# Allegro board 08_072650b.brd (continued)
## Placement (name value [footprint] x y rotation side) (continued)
DS20  APHHS1005LSECK/J3-PF  [LED0402H24]  5.15 77.42 0 top
DS21  APHHS1005LSECK/J3-PF  [LED0402H24]  5.15 78.94 0 top
DS22  APHHS1005LCGCK  [LED0402_A]  5.15 75.77 0 top
DS23  APHHS1005LCGCK  [LED0402_A]  5.15 80.47 0 top
DS24  APHHS1005LCGCK  [LED0402_A]  5.15 82.12 0 top
DS25  APHHS1005LCGCK  [LED0402_A]  5.15 83.77 0 top
DS26  APHHS1005LCGCK  [LED0402_A]  5.15 85.29 0 top
DS27  APHHS1005LCGCK  [LED0402_A]  5.15 86.82 0 top
DS29  SML-LX1206IW-TR  [LEDSML126W63H43]  43.18 190.58 90 top
DS31  APHHS1005LSECK/J3-PF  [LED0402H24]  206.88 113.08 90 top
E1  120OHM  [L0402]  10.39 229.39 270 bottom
E2  600OHM  [L0603_A]  131.83 153.52 180 bottom
E2B  120OHM  [L0402#2]  34.61 232.11 180 bottom
E3  600OHM  [L0603_A]  128.4 166.5 270 bottom
E4  600OHM  [L0603_A]  127.71 174.47 270 bottom
E5  600OHM  [L0603_A]  119.79 174.42 270 bottom
E7  120OHM  [L0402#2]  6.71 224.59 0 bottom
E8  120OHM  [L0402]  14.58 231.29 90 top
E9  120OHM  [L0402]  23.24 223.88 0 bottom
E10  120OHM  [L0402#2]  16.61 231.83 90 top
E11  120OHM  [L0402]  18.14 219.35 90 top
E12  120OHM  [L0402]  11.4 216.31 270 bottom
E13  120OHM  [L0402]  23.6 218.85 270 bottom
E14  120OHM  [L0402]  20.29 225.32 270 top
E15  30OHM  [L0402]  30.18 195.33 270 top
E20  50OHM AT 100MEGHZ  [L1206-3]  171.86 204.06 180 bottom
E21  470OHM AT 100MEGHZ  [L1206H71]  229.41 173.53 270 top
E22  470OHM AT 100MEGHZ  [L1206H71]  225.6 173.53 270 top
E23  50OHM AT 100MEGHZ  [L1206-3]  171.42 216.56 180 bottom
E24  50OHM AT 100MEGHZ  [L1206-3]  175.69 225.96 180 bottom
E26  50OHM AT 100MEGHZ  [L1206-3]  175.64 222.02 180 bottom
E27  50OHM AT 100MEGHZ  [L1206-3]  175.69 229.59 180 bottom
E30  50OHM AT 100MEGHZ  [L1206-3]  184.91 75.12 180 top
E31  50OHM AT 100MEGHZ  [L1206-3]  190.92 71.81 270 top
EXT_HMCREF  142-0701-201  [CNJOHNSON142-0701-201]  47.23 276.81 180 top
EXT_SYNC  142-0701-201  [CNJOHNSON142-0701-201]  8.56 243.32 0 top
EXT_SYS_N  142-0701-201  [CNJOHNSON142-0701-201]  15.21 276.66 0 top
EXT_SYS_P  142-0701-201  [CNJOHNSON142-0701-201]  31.12 276.68 0 top
EXT_TRIG  142-0701-201  [CNJOHNSON142-0701-201]  8.71 259.92 0 top
F1  12A  [F1206H46]  211.48 262.61 270 top
FANPWM  WHT  [CNKEY5001TP]  216.53 222.88 0 top
FMC12I  WHT  [CNKEY5001TP]  224.03 252.48 0 top
FMC12O  WHT  [CNKEY5001TP]  89.56 22.43 0 top
GND1  BLK  [CNKEY5001TP]  9.27 100.97 0 top
GND2  BLK  [CNKEY5001TP]  200.46 236.4 0 top
GND3  BLK  [CNKEY5001TP]  57.81 260.99 180 bottom
GND4  BLK  [CNKEY5001TP]  49.99 194.84 0 top
GND5  BLK  [CNKEY5001TP]  4.34 49 180 bottom
GND6  BLK  [CNKEY5001TP]  218.06 38.07 180 bottom
GND7  BLK  [CNKEY5001TP]  173.02 82.4 0 top
GND8  BLK  [CNKEY5001TP]  174.98 164.64 180 bottom
J3  85305-0232  [CNSMASQ197H161]  144.2 10.24 270 top
J12  142-0701-201  [CNJOHNSON142-0701-201]  41.58 259.82 0 top
J13  142-0701-201  [CNJOHNSON142-0701-201]  26.35 259.83 0 top
J17  142-0701-201  [CNJOHNSON142-0701-201]  49.61 247.28 270 top
J18  142-0701-201  [CNJOHNSON142-0701-201]  65.09 247.38 90 top
JP1  0  [R0402]  11.63 93.91 270 top
JP2  0  [R0402]  42.37 103.07 270 top
L1  1.3NH  [L0201_A]  126.24 150.52 180 bottom
L2  4.7uH  [L0806]  191.26 191.72 0 bottom
L3  1.3NH  [L0201_A]  121.97 151.54 0 bottom
L4  1.3NH  [L0201_A]  123.42 151.54 0 bottom
L5  72NH  [LSML299W295H195]  188.59 48.03 180 top
L6  1UH  [L0806_DFE]  84.38 212.87 180 top
L8  0.13UH  [LSMSQ157H122]  190.25 60.92 180 top
L9  0.13UH  [LSMSQ157H122]  200.33 82.17 90 top
L10  1.3NH  [L0201_A]  125.07 150.52 180 bottom
L11  0.47UH  [L0603]  160.48 41.3 90 bottom
L15  3.6nH  [L0201]  36.91 218.92 0 top
L16  3.6nH  [L0201]  36.93 218.26 0 top
L17  10UH  [L1210H47]  219.89 253.45 0 top
L18  0.13UH  [LSMSQ157H122]  197.21 74.45 180 top
L19  1UH  [L0806_DFE]  71.04 212.73 180 top
L20  0.33UH  [L1008H47]  109.52 261.21 270 top
L21  0.22UH  [L2520H47]  205.56 101.22 180 top
NOREF  -  []  0 34.04 0 top
NOREF#2  -  []  241.43 33.91 90 top
NOREF#3  -  []  -258.06 -177.93 0 top
NOREF#4  -  []  -258.06 -177.93 0 top
NOREF#5  -  []  6.16 39.88 0 top
NOREF#6  -  []  156.72 0 90 top
NOREF#7  -  []  37.72 119.46 90 top
NOREF#8  -  []  241.36 33.89 90 top
NOREF#9  -  [unnamed#2]  95.4 152.48 0 top
NOREF#10  -  [unnamed#2]  229.36 38.35 0 top
NOREF#11  -  [unnamed#2]  152.86 27.76 90 top
NOREF#12  -  []  0 34.04 0 top
NOREF#13  -  []  141.99 272.92 0 top
NOREF#14  -  [unnamed#2]  234.8 160.07 225 top
NOREF#15  -  []  371.86 -35.69 0 top
NOREF#16  -  []  241.24 289.35 180 top
NOREF#17  -  []  0.06 34.01 0 top
NOREF#18  -  []  86.3 0.04 0 top
NOREF#19  -  [unnamed#2]  117.96 281.99 225 top
NOREF#20  -  []  156.65 0.04 90 top
NOREF#21  -  []  0 289.43 0 top
NOREF#22  -  [unnamed#2]  11.18 284.1 0 top
NOREF#23  -  []  6.16 39.88 0 top
NOREF#24  -  []  156.72 0 0 top
NOREF#25  -  [unnamed#2]  235.2 40.39 225 top
NOREF#26  -  [unnamed#2]  95.4 98.5 0 top
NOREF#27  -  []  131.01 322.3 0 top
NOREF#28  -  []  -12.11 51.06 0 top
NOREF#29  -  [unnamed#2]  5.33 162.56 225 top
NOREF#30  -  []  86.23 0 0 top
NOREF#31  -  [unnamed#2]  149.38 152.48 0 top
NOREF#32  -  []  -258.06 -177.93 0 top
NOREF#33  -  []  86.23 0 0 top
NOREF#34  -  [unnamed#2]  149.38 98.5 0 top
NOREF#35  -  [unnamed#2]  6.16 39.88 225 top
NOREF#36  -  []  152.53 -60.58 0 top
NOREF#37  -  [unnamed#2]  234.8 281.99 225 top
NOREF#38  -  [unnamed#2]  11.18 38.35 0 top
NOREF#39  VAL  [unnamed#3]  202.18 121.26 270 top
NOREF#40  -  []  49.76 -121.69 0 top
NOREF#41  -  [unnamed#2]  5.33 284.48 225 top
NOREF#42  -  [unnamed#2]  89.86 27.76 90 top
NOREF#43  -  []  0.06 289.35 270 top
NOREF#44  -  []  203.53 217.7 180 bottom
P1  ASP-188588-01  [CNSAMTECASP-188588-01]  121.28 25.78 180 bottom
P2  FTSH-108-01-F-DV-K  [CNHDR2X8H251]  49.33 45.49 270 top
P3  FTSH-110-01-L-DV-K  [CNHDR2X10H251]  48.18 66.19 270 top
P4  10103594-0001LF  [CNFCI10103594-0001LF]  0 59.05 90 bottom
P5  DF3EA-4P-2H(51)  [CNHIROSEDF3EA-2P-2H]  237.39 118.57 270 bottom
P7  TSM-103-01-T-SV  [CNSM1X3H380]  236.47 119.43 90 top
P18  CJT-T-P-HH-RA-TH1  [CNSAMTECCJT-T-P-GF-RA-TH1]  3.25 192.23 90 top
P19  CJT-T-P-HH-RA-TH1  [CNSAMTECCJT-T-P-GF-RA-TH1]  3.1 200.28 90 top
P22  39-30-1060  [CNHDRRA2X3H451]  211.48 272.52 0 top
P23  22-11-2032  [CNMOLEX22-23-2031]  231.57 227.66 270 top
PWRDBG  TMM-102-01-G-S-SM  [CNSAMTECTMM-102-01-G-S-SM]  191.16 247.5 180 top
Q1  DMN2300UFL4-7  [DFN6_1_3X1]  235.4 233.55 270 bottom
Q2  DMN2300UFL4-7  [DFN6_1_3X1]  235.3 256.78 90 bottom
Q3  DMN2300UFL4-7  [DFN6_1_3X1]  235.34 239.5 90 bottom
Q4  DMN2300UFL4-7  [DFN6_1_3X1]  235.33 251.59 90 bottom
Q5  DMN2300UFL4-7  [DFN6_1_3X1]  235.28 245.74 270 bottom
Q6  DMN2300UFL4-7  [DFN6_1_3X1]  235.3 263.19 90 bottom
Q7  2N7002T  [SOT523F]  191.54 258.8 180 top
Q8  DMN2300UFL4-7  [DFN6_1_3X1]  114.3 154.81 90 bottom
Q9  DMN2300UFL4-7  [DFN6_1_3X1]  224.87 123.44 90 top
Q10  DMN2300UFL4-7  [DFN6_1_3X1]  210.9 112.75 180 bottom
Q11  DMN2300UFL4-7  [DFN6_1_3X1]  202.41 114.55 270 bottom
Q13  NTS4101PT1G  [SC-70-3]  224.56 118.9 270 top
Q14  NTS4101PT1G  [SC-70-3]  225.48 114.53 90 bottom
Q15  NTS4101PT1G  [SC-70-3]  225.48 111.61 90 bottom
Q16  BSC0504NSIATMA1  [SON8]  203.1 271.88 180 top
Q17  SI2336DS-T1-GE3  [SOT23]  222.17 221.95 270 top
Q18  NTS4101PT1G  [SC-70-3]  221.77 123.32 180 top
Q22  NTS4101PT1G  [SC-70-3]  224.49 115.77 270 top
R1  56.2  [R0402]  24.74 221.8 180 bottom
R2  49.9  [R0402]  26.8 229.31 0 bottom
R3  56.2  [R0402]  23.46 228.8 270 bottom
R4  1K  [R0402]  22.2 217.2 270 bottom
R5  0  [R0402]  10.07 223.67 90 top
R6  100  [R0402]  24.49 225.83 270 bottom
R7  0  [R0402]  11.6 224.23 0 top
R8  10K  [R0402]  6.8 220.76 180 bottom
R9  10K  [R0402]  6.8 219.77 180 bottom
R10  430  [R0402]  27.4 218.63 0 bottom
R11  11K  [R0402]  20.44 232.67 180 bottom
R12  0  [R0402]  24.54 272.62 180 top
R13  0  [R0402]  131.7 162.53 180 bottom
R14  0  [R0402]  22.25 272.69 0 top
R15  0  [R0402]  22.81 273.2 90 top
R16  0  [R0402]  42.27 193.09 0 bottom
R17  0  [R0402]  42.19 194.18 0 bottom
R18  0.04  [R0603]  214.38 164.85 180 top
R19  44.2K  [R0402]  80.04 218.36 270 bottom
R20  0  [R0402]  133.63 255.12 270 bottom
R21  0  [R0402]  132.49 255.12 270 bottom
R22  10K  [R0402]  139.14 280.34 0 top
R23  0  [R0402]  102.14 238.25 90 bottom
R24  0  [R0402]  106.48 238.2 90 bottom
R25  10K  [R0402]  158.45 47.22 270 bottom
R26  3.01K  [R0402]  78.87 217.34 270 bottom
R28  100  [R0402]  56.47 239.46 270 bottom
R29  100  [R0402]  60.96 239.88 270 bottom
R31  0  [R0402]  95.91 238.38 180 bottom
R32  0  [R0402]  96.93 237.24 180 bottom
R33  0  [R0402]  118.54 237.44 0 bottom
R34  0  [R0402]  117.53 238.58 0 bottom
R35  0  [R0402]  118.52 240.23 0 bottom
R36  0  [R0402]  117.5 241.38 0 bottom
R38  0  [R0402]  95.91 240.67 180 bottom
R39  0  [R0402]  96.93 239.52 180 bottom
R40  0  [R0402]  118.52 235.03 0 bottom
R41  0  [R0402]  117.5 236.17 0 bottom
R42  0  [R0402]  118.52 242.65 0 bottom
R43  0  [R0402]  117.5 243.79 0 bottom
R44  0  [R0402]  95.91 242.95 180 bottom
R45  0  [R0402]  96.93 241.81 180 bottom
R46  0  [R0402]  118.52 232.61 0 bottom
R47  0  [R0402]  117.5 233.76 0 bottom
R48  0  [R0402]  118.52 245.06 0 bottom
R49  0  [R1206]  130.12 284.66 270 top
R50  0  [R0402]  117.5 246.2 0 bottom
R51  0  [R0402]  84.29 239.76 270 bottom
R52  1MEG  [R0402]  84.59 226.18 0 bottom
R53  1MEG  [R0402]  86.23 226.9 270 bottom
R54  38.3K  [R0402]  112.34 268.94 90 bottom
R55  0  [R0402]  191.16 256.64 180 top
R56  150  [R0402]  79.73 241.39 0 bottom
R57  150  [R0402]  81.32 239.38 180 bottom
R58  0  [R0402]  131.34 255.12 270 bottom
R59  49.9K  [R0402]  81.67 221.01 180 bottom
R60  100K  [R0402]  113.31 274.27 90 bottom
R61  49.9K  [R0402]  219.66 225.15 270 top
R62  10  [R0402]  234.19 74.83 0 bottom
R63  10  [R0402]  116.64 264.06 270 top
R64  100  [R0402]  194.03 266.42 270 top
R65  2.1K  [R0402]  196.01 262.48 270 top
R66  750  [R0201]  228.07 103.48 90 bottom
R67  750  [R0201]  140.28 269.52 90 bottom
R68  10K  [R0201]  209.17 119.76 270 top
R69  0  [R0201]  144.04 272.39 90 bottom
R70  0  [R0201]  131.24 272.47 90 bottom
R71  0.005  [R1206H20]  203.86 262.61 90 top
R72  0  [R0201]  70.77 176.67 90 top
R73  0  [R0201]  226.85 103.48 90 bottom
R74  0  [R0402]  140.28 271.73 90 bottom
R75  0  [R0201]  164.58 192.45 310 top
R76  0  [R0201]  80.32 192.89 50 top
R77  0  [R0201]  173.81 176.26 270 top
R78  10K  [R0201]  202.9 121.26 270 top
R79  0  [R0201]  199.19 144.81 270 bottom
R80  0  [R0201]  201.17 144.78 270 bottom
R81  0  [R0201]  203.53 144.81 270 bottom
R83  0  [R0402]  129.46 238.23 180 bottom
R84  0  [R0402]  130.48 237.08 180 bottom
R85  0  [R0402]  154.86 238.35 0 bottom
R86  0  [R0402]  153.85 239.5 0 bottom
R87  0  [R0402]  154.74 241.15 0 bottom
R88  0  [R0402]  153.72 242.29 0 bottom
R89  0  [R0402]  129.46 240.51 180 bottom
R90  0  [R0402]  130.48 239.37 180 bottom
R91  0  [R0402]  154.74 235.94 0 bottom
R92  0  [R0402]  153.72 237.08 0 bottom
R93  0  [R0402]  154.74 243.56 0 bottom
R94  0  [R0402]  153.72 244.7 0 bottom
R95  0  [R0402]  129.46 242.8 180 bottom
R96  0  [R0402]  130.48 241.66 180 bottom
R97  0  [R0402]  154.74 233.53 0 bottom
R98  0  [R0402]  153.72 234.67 0 bottom
R99  0  [R0402]  154.74 245.97 0 bottom
R100  0  [R0402]  153.72 247.12 0 bottom
R101  0  [R1206]  198.15 221.79 180 top
R102  0  [R1206]  198.15 217.22 180 top
R103  150  [R0201]  9.98 225.86 0 bottom
R104  0  [R0402]  187.6 229.41 90 bottom
R105  0  [R0402]  186.46 228.4 90 bottom
R106  0  [R0402]  186.97 205.54 270 bottom
R107  0  [R0402]  188.11 206.55 270 bottom
R108  0  [R0402]  191.16 205.54 270 bottom
R109  0  [R0402]  192.3 206.55 270 bottom
R110  0  [R0402]  190.02 229.41 90 bottom
R111  0  [R0402]  188.87 228.4 90 bottom
R112  0  [R0402]  184.56 205.54 270 bottom
R113  0  [R0402]  185.7 206.55 270 bottom
R114  0  [R0402]  193.57 205.54 270 bottom
R115  0  [R0402]  194.72 206.55 270 bottom
R116  0  [R0402]  192.43 229.41 90 bottom
R117  0  [R0402]  191.29 228.4 90 bottom
R118  0  [R0402]  182.14 205.54 270 bottom
R119  0  [R0402]  183.29 206.55 270 bottom
R120  0  [R0402]  195.99 205.54 270 bottom
R121  0  [R0402]  197.13 206.55 270 bottom
R123  0.04  [R0603]  213.66 154.36 180 top
R124  1K  [R0402]  211.86 160.58 0 bottom
R125  1K  [R0402]  210.67 150.85 0 bottom
R126  10.2K  [R0402]  204.42 148.46 0 bottom
R127  10.2K  [R0402]  205.1 158.88 0 bottom
R128  30.1K  [R0402]  201.75 152.68 90 bottom
R129  30.1K  [R0402]  202.39 163.19 90 bottom
R130  64.9K  [R0402]  201.75 154.64 90 bottom
R131  64.9K  [R0402]  202.44 165.23 90 bottom
R132  100  [R0402]  24.74 227.86 270 bottom
R133  14K  [R0402]  146.51 269.54 90 bottom
R134  0  [R0201]  217.65 118.87 90 bottom
R135  0  [R0201]  198.88 129.18 0 bottom
R136  100  [R0201]  207.92 119.86 0 bottom
R137  0  [R1206]  142.95 284.66 270 top
R138  0  [R0201]  213.87 136.75 270 bottom
R139  0  [R0201]  215.06 136.73 270 bottom
R140  137K  [R0402]  144.09 269.54 90 bottom
R141  0  [R0201]  213.89 134.47 270 bottom
R142  5.49K  [R0402]  218.03 120.73 90 top
R143  5.49K  [R0402]  218.34 124 270 top
R144  14K  [R0402]  133.2 269.29 270 bottom
R145  178K  [R0402]  130.63 269.27 270 bottom
R146  0  [R0402]  136.8 278.18 0 bottom
R147  100K  [R0402]  148.79 273.35 90 bottom
R148  0  [R0402]  126.31 278.18 180 bottom
R149  0  [R0402]  229.49 116.36 0 bottom
R150  10K  [R0201]  224.59 129.34 0 bottom
R151  10K  [R0201]  224.59 131.06 0 bottom
R152  10K  [R0201]  224.59 130.48 0 bottom
R153  10K  [R0201]  224.59 129.92 0 bottom
R154  10K  [R0201]  224.59 127.15 0 bottom
R155  10K  [R0201]  224.59 127.69 0 bottom
R156  10K  [R0201]  224.59 128.78 0 bottom
R157  10K  [R0201]  224.59 128.22 0 bottom
R158  2.1K  [R0402]  208.58 115.49 180 top
R159  0  [R0402]  146 277.29 180 bottom
R160  0  [R0402]  106.45 12.6 0 top
R161  10K  [R0402]  95.99 12.42 180 top
R162  0  [R0402]  106.53 11.51 180 top
R163  51K  [R0402]  43.1 61.62 180 top
R164  0  [R0402]  53.14 71.91 0 top
R165  0  [R0402]  53.14 69.37 0 top
R166  0  [R0402]  53.14 62.89 0 top
R167  0  [R0402]  53.14 70.64 0 top
R168  0  [R0402]  53.14 68.1 0 top
R169  78.7K  [R0402]  148.82 271.27 270 bottom
R170  0  [R0402]  59.19 45.01 0 top
R171  0  [R0402]  61.6 45.01 0 top
R172  0  [R0402]  61.6 42.34 0 top
R173  0  [R0402]  59.19 46.15 0 top
R174  0  [R0402]  61.6 46.15 0 top
R175  0  [R0402]  61.6 41.2 0 top
R176  0  [R0402]  59.19 47.29 0 top
R177  0  [R0402]  61.6 47.29 0 top
R178  0  [R0402]  61.6 43.48 0 top
R179  0  [R0402]  61.6 40.06 0 top
R180  0  [R0402]  59.19 48.44 0 top
R181  0  [R0402]  61.6 48.44 0 top
R182  0  [R0402]  43.73 84.56 0 top
R183  0  [R0402]  83.01 70.97 270 top
R184  0  [R0402]  43.73 82.27 0 top
R185  0  [R0402]  43.73 79.99 0 top
R186  0  [R0402]  80.72 70.97 270 top
R187  0  [R0402]  78.44 70.97 270 top
R188  0  [R0402]  68.51 71.07 270 top
R189  0  [R0402]  66.22 71.07 270 top
R190  0  [R0402]  63.94 71.07 270 top
R191  0  [R0402]  43.73 85.7 0 top
R192  0  [R0402]  43.73 78.84 0 top
R193  0  [R0402]  84.15 70.97 270 top
R194  0  [R0402]  77.3 70.97 270 top
R195  0  [R0402]  69.65 71.07 270 top
R196  0  [R0402]  62.79 71.07 270 top
R197  0  [R0402]  43.73 83.42 0 top
R198  0  [R0402]  43.73 81.13 0 top
R199  0  [R0402]  43.73 77.7 0 top
R200  0  [R0402]  81.87 70.97 270 top
R201  0  [R0402]  79.58 70.97 270 top
R202  0  [R0402]  76.15 70.97 270 top
R203  0  [R0402]  67.36 71.07 270 top
R204  0  [R0402]  65.08 71.07 270 top
R205  0  [R0402]  61.65 71.07 270 top
R206  0  [R0402]  71.76 44.88 0 top
R207  0  [R0402]  53.89 82.15 0 top
R208  0  [R0402]  80.6 60.81 270 top
R209  0  [R0402]  66.09 60.91 270 top
R210  0  [R0402]  71.76 46.02 0 top
R211  0  [R0402]  53.89 83.29 0 top
R212  0  [R0402]  81.74 60.81 270 top
R213  0  [R0402]  71.76 43.74 0 top
R214  0  [R0402]  53.89 81 0 top
R215  0  [R0402]  79.45 60.81 270 top
R216  0  [R0402]  67.24 60.91 270 top
R217  0  [R0402]  64.95 60.91 270 top
R218  0  [R0402]  71.76 47.17 0 top
R219  0  [R0402]  53.89 84.43 0 top
R220  0  [R0402]  82.88 60.81 270 top
R221  0  [R0402]  71.76 42.6 0 top
R222  0  [R0402]  53.89 79.86 0 top
R223  0  [R0402]  78.31 60.81 270 top
R224  0  [R0402]  68.38 60.91 270 top
R225  0  [R0402]  71.76 40.31 0 top
R226  0  [R0402]  53.89 77.57 0 top
R227  0  [R0402]  76.03 60.81 270 top
R228  0  [R0402]  63.81 60.91 270 top
R229  0  [R0402]  61.52 60.91 270 top
R230  0  [R0402]  71.76 48.31 0 top
R231  0  [R0402]  71.76 41.45 0 top
R232  0  [R0402]  53.89 85.58 0 top
R233  0  [R0402]  53.89 78.72 0 top
R234  0  [R0402]  84.03 60.81 270 top
R235  0  [R0402]  77.17 60.81 270 top
R236  0  [R0402]  69.52 60.91 270 top
R237  0  [R0402]  62.67 60.91 270 top
R238  0  [R0402]  83.21 88.03 270 top
R239  100  [R0201]  37.19 105.51 270 top
R240  0  [R0402]  22.51 105.79 270 top
R241  0  [R0402]  80.93 88.03 270 top
R242  0  [R0402]  78.64 88.03 270 top
R243  100  [R0201]  34.9 105.51 270 top
R244  100  [R0201]  32.62 105.51 270 top
R245  0  [R0402]  20.22 105.79 270 top
R246  0  [R0402]  17.94 105.79 270 top
R247  0  [R0402]  84.36 88.03 270 top
R248  0  [R0402]  77.5 88.03 270 top
R249  100  [R0201]  38.33 105.51 270 top
R250  100  [R0201]  31.47 105.51 270 top
R251  100  [R0201]  23.65 105.79 270 top
R252  0  [R0402]  16.79 105.79 270 top
R253  0  [R0402]  82.07 88.03 270 top
R254  0  [R0402]  79.78 88.03 270 top
R255  0  [R0402]  76.33 88.01 270 top
R256  100  [R0201]  36.05 105.51 270 top
R257  100  [R0201]  33.76 105.51 270 top
R258  100  [R0201]  30.33 105.51 270 top
R259  0  [R0402]  21.36 105.79 270 top
R260  0  [R0402]  19.08 105.79 270 top
R261  0  [R0402]  15.65 105.79 270 top
R262  0  [R0402]  80.8 77.87 270 top
R263  100  [R0201]  34.78 95.35 270 top
R264  0  [R0402]  20.53 95.65 270 top
R265  0  [R0402]  81.94 77.87 270 top
R266  100  [R0201]  35.92 95.35 270 top
R267  0  [R0402]  21.67 95.65 270 top
R268  0  [R0402]  79.66 77.87 270 top
R269  100  [R0201]  33.63 95.35 270 top
R270  0  [R0402]  19.38 95.65 270 top
R271  0  [R0402]  83.09 77.87 270 top
R272  100  [R0201]  37.06 95.35 270 top
R273  0  [R0402]  22.81 95.65 270 top
R274  0  [R0402]  78.51 77.87 270 top
R275  100  [R0201]  32.49 95.35 270 top
R276  0  [R0402]  18.24 95.65 270 top
R277  0  [R0402]  76.23 77.87 270 top
R278  100  [R0201]  30.08 95.35 270 top
R279  0  [R0402]  15.95 95.65 270 top
R280  0  [R0402]  84.23 77.87 270 top
R281  0  [R0402]  77.37 77.87 270 top
R282  100  [R0201]  38.2 95.35 270 top
R283  100  [R0201]  31.3 95.35 270 top
R284  100  [R0201]  23.96 95.65 270 top
R285  0  [R0402]  17.1 95.65 270 top
R286  931  [R0603]  134.26 157.68 180 bottom
R287  30  [R0603]  135.15 161.57 90 bottom
R288  0  [R0402]  129.51 153.04 270 bottom
R289  324  [R0603]  133.53 161.57 270 bottom
R290  0  [R0402]  130 151.43 0 bottom
R291  0  [R0402]  128.6 160.58 270 bottom
R292  49.9  [R0402]  124.94 162.97 0 bottom
R293  0  [R0201]  34.59 255.72 90 bottom
R294  0  [R0201]  34.02 255.72 90 bottom
R295  200  [R0402]  116.36 150.77 180 bottom
R296  49.9  [R0402]  122.83 162.97 0 bottom
R297  100  [R0402]  118.36 161.47 225 bottom
R298  100  [R0201]  122.32 135.75 90 bottom
R299  100  [R0201]  113.89 133.73 180 bottom
R300  100  [R0201]  130.71 133.73 0 bottom
R301  0  [R0402]  137.46 136.17 0 bottom
R302  0  [R0402]  107.39 136.07 180 bottom
R303  10K  [R0402]  116.28 154.43 180 bottom
R304  0  [R1206]  104.62 237.39 270 bottom
R305  62  [R0402]  57.58 236.12 90 bottom
R306  0  [R0402]  58.85 236.12 270 bottom
R307  10K  [R0201]  61.54 228.22 180 bottom
R308  10K  [R0201]  60.53 225.3 180 bottom
R309  10K  [R0201]  61.54 227.58 180 bottom
R310  10K  [R0201]  61.54 227 180 bottom
R311  10K  [R0201]  59.33 234.26 0 bottom
R312  10K  [R0201]  60.58 234.24 180 bottom
R313  464  [R0402]  131.11 134.62 180 bottom
R314  464  [R0402]  113.51 134.54 0 bottom
R315  0  [R0402]  129.64 162.53 180 bottom
R316  0  [R0402]  116.33 151.99 180 bottom
R317  0  [R0402]  116.31 153.14 180 bottom
R318  10K  [R0402]  112.78 155.19 270 bottom
R319  100  [R0201]  105.33 117.37 90 bottom
R320  100  [R0201]  104.67 112.67 270 bottom
R321  0  [R0201]  104.42 117.09 180 bottom
R322  0  [R0201]  104.42 117.65 180 bottom
R323  0  [R0201]  103.76 112.93 180 bottom
R324  0  [R0201]  103.76 112.39 180 bottom
R325  1K  [R0402]  141.1 107.26 0 top
R326  1K  [R0402]  143.05 107.26 180 top
R327  0  [R0201]  104.42 115.75 180 bottom
R328  0  [R0201]  104.42 116.36 180 bottom
R329  0  [R0201]  104.32 114.12 180 bottom
R330  0  [R0201]  104.34 114.71 180 bottom
R331  100K  [R0402]  237.02 234.23 90 bottom
R332  100K  [R0402]  233.65 257.68 90 bottom
R333  100K  [R0402]  233.72 234.25 90 bottom
R334  0  [R1206]  222.33 217.73 180 top
R335  78.7K  [R0402]  135.56 271.96 270 bottom
R336  100K  [R0402]  236.96 257.66 90 bottom
R337  49.9K  [R0402]  221.56 224.64 0 top
R338  100K  [R0402]  233.69 240.4 90 bottom
R339  100K  [R0402]  233.72 252.23 90 bottom
R340  10  [R0402]  147.65 280.59 90 top
R341  10  [R0402]  134.82 280.59 90 top
R342  100K  [R0402]  236.99 240.38 90 bottom
R343  100K  [R0402]  237.02 252.22 90 bottom
R344  2.1K  [R0402]  232.38 267 180 top
R345  2.1K  [R0402]  232.3 256.15 180 top
R346  2.1K  [R0402]  232.31 262.56 180 top
R347  2.1K  [R0402]  232.37 234.12 180 top
R348  2.1K  [R0402]  232.37 232.72 180 top
R349  2.1K  [R0402]  232.34 238.87 180 top
R350  2.1K  [R0402]  232.34 240.26 180 top
R351  2.1K  [R0402]  232.32 246.31 180 top
R352  2.1K  [R0402]  232.37 252.1 180 top
R353  2.1K  [R0402]  232.37 250.7 180 top
R354  2.1K  [R0402]  232.3 257.54 180 top
R355  2.1K  [R0402]  232.32 244.91 180 top
R356  2.1K  [R0402]  232.31 263.96 180 top
R357  100K  [R0402]  236.97 246.43 90 bottom
R358  100K  [R0402]  233.65 264.09 90 bottom
R359  100K  [R0402]  233.67 246.44 90 bottom
R360  100K  [R0402]  236.96 264.08 90 bottom
R361  0  [R1206]  96.06 260.71 180 bottom
R362  0  [R1206]  91.8 262.53 270 bottom
R363  0  [R1206]  86.79 251.21 180 bottom
R364  0  [R1206]  86.79 253.8 180 bottom
R365  0.003  [R1206]  141.3 262.38 270 top
R366  0.003  [R1206]  135.86 262.41 270 top
R367  0  [R0402]  227.51 182.55 90 bottom
R368  24.9K  [R0402]  220.09 193.27 270 bottom
R369  0  [R0402]  231.19 176.89 180 top
R370  0  [R0201]  207.34 140.26 0 bottom
R371  0  [R0402]  226.24 182.55 90 bottom
R372  34.8K  [R0402]  221.36 193.29 270 bottom
R373  0  [R0402]  230.91 145.11 90 top
R374  0  [R0402]  229.44 120.4 0 bottom
R379  10K  [R0402]  234.57 52.86 0 bottom
R380  147K  [R0402]  216.41 193.24 90 bottom
R381  196K  [R0201]  225.2 192.07 0 bottom
R382  147K  [R0402]  217.91 193.29 90 bottom
R385  150  [R0201]  9.98 226.44 0 bottom
R386  10  [R0402]  214.4 182.42 270 bottom
R387  10  [R0402]  215.7 182.42 270 bottom
R388  10  [R0402]  218.26 182.42 270 bottom
R389  100  [R0201]  17.37 216.56 180 bottom
R390  100  [R0201]  16.18 216.48 180 bottom
R391  100  [R0201]  13.13 216.41 180 bottom
R392  100  [R0201]  14.33 216.46 180 bottom
R393  100  [R0201]  15.34 233.58 0 bottom
R394  100  [R0201]  19.41 216.56 180 bottom
R395  100  [R0201]  20.68 216.56 180 bottom
R396  10K  [R0402]  101.03 6.45 0 top
R397  10K  [R0402]  132.11 4.13 270 top
R398  10K  [R0402]  90.74 9.75 180 top
R399  10K  [R0402]  103.37 7.26 180 top
R400  10K  [R0402]  119.41 8.12 90 top
R401  10K  [R0402]  127.33 4.15 270 top
R402  10K  [R0402]  112.94 6.48 0 top
R403  10K  [R0402]  125.6 5.31 270 top
R404  0  [R0402]  42.67 76.56 0 top
R405  0  [R0402]  39.9 78.44 0 top
R406  0  [R0402]  39.92 79.99 0 top
R407  0  [R0402]  39.95 81.49 0 top
R408  10  [R0402]  216.99 182.42 270 bottom
R409  0  [R1206]  231.6 192.15 0 top
R410  0  [R0402]  13.44 231.04 270 bottom
R411  0  [R1206]  211.1 189.48 180 top
R412  0  [R1206]  227.66 181.46 0 top
R413  0  [R0402]  12.55 231.04 270 bottom
R415  0.002  [R0805]  138.56 258.32 270 top
R416  0  [R0402]  189.41 193.8 270 bottom
R417  0  [R0402]  190.53 193.8 270 bottom
R418  0  [R0402]  196.04 190.86 90 bottom
R419  0  [R0201]  235.61 133.45 180 bottom
R420  10K  [R0402]  193.88 190.68 0 bottom
R421  0  [R0402]  200.76 190.91 0 bottom
R422  0  [R0402]  200.76 192.79 0 bottom
R423  0  [R0402]  192.74 195.66 90 bottom
R424  0  [R0402]  193.57 195.66 90 bottom
R425  10K  [R0402]  235.2 73.56 0 bottom
R426  10K  [R0402]  235.2 71.15 0 bottom
R427  10K  [R0402]  234.57 51.71 0 bottom
R428  10K  [R0402]  235.2 75.97 0 bottom
R429  10K  [R0402]  234.57 44.73 0 bottom
R430  10K  [R0402]  234.57 49.43 0 bottom
R431  10K  [R0402]  234.57 48.29 0 bottom
R432  10K  [R0402]  234.57 47.14 0 bottom
R433  0  [R0402]  229.49 117.53 180 bottom
R434  0  [R0402]  229.44 121.56 180 bottom
R435  14.3K  [R0402]  214.77 41.74 90 bottom
R436  14.3K  [R0402]  211.27 79.96 270 bottom
R437  14.3K  [R0402]  213.68 79.96 270 bottom
R438  14.3K  [R0402]  217.99 41.76 90 bottom
R439  14.3K  [R0402]  216.1 79.96 270 bottom
R440  14.3K  [R0402]  218.51 79.96 270 bottom
R441  32.4K  [R0402]  213.51 41.78 270 bottom
R442  32.4K  [R0402]  210.13 78.94 90 bottom
R443  787  [R0402]  212.52 78.94 270 bottom
R444  787  [R0402]  219.13 42.77 270 bottom
R445  1.65K  [R0402]  214.95 78.94 90 bottom
R446  49.9K  [R0402]  222.3 113.77 0 bottom
R447  2.43K  [R0402]  217.37 78.94 90 bottom
R448  49.9K  [R0402]  222.22 111.48 0 bottom
R449  32.4K  [R0402]  216.15 42.82 90 bottom
R450  22.6K  [R0402]  208.79 78.89 270 bottom
R451  0.03  [R1206-2]  234.67 107.14 270 top
R452  0.3  [R1206-2]  176.05 39.75 180 bottom
R453  0  [R0402]  103.58 279.63 180 top
R454  28K  [R0402]  66.7 218.21 270 bottom
R455  3.01K  [R0402]  65.53 217.2 270 bottom
R456  33.2K  [R0402]  68.38 221.59 180 bottom
R457  0  [R1206]  72.92 219.76 90 bottom
R458  10K  [R0402]  14.96 90.3 270 top
R459  300  [R0402]  7.82 72.85 180 top
R460  300  [R0402]  7.82 74.37 180 top
R461  300  [R0402]  7.82 77.42 180 top
R462  300  [R0402]  7.82 78.94 180 top
R463  300  [R0402]  7.82 75.77 180 top
R464  300  [R0402]  7.82 80.47 180 top
R465  300  [R0402]  7.82 82.12 180 top
R466  300  [R0402]  7.82 83.77 180 top
R467  300  [R0402]  7.82 85.29 180 top
R468  300  [R0402]  7.82 86.82 180 top
R469  10K  [R0402]  12.5 55.6 180 top
R470  0  [R0201]  223.84 102.01 0 bottom
R471  0  [R0201]  108.84 272.03 90 bottom
R472  0  [R0201]  216.05 143.08 270 bottom
R473  10K  [R0201]  82.93 227.2 90 bottom
R474  10K  [R0201]  81.69 227.2 270 bottom
R476  0  [R0201]  175.16 202.56 270 bottom
R479  0  [R0201]  177.6 207.92 270 bottom
R482  1K  [R0402]  182.91 273.02 0 top
R483  0.2  [R0402]  218.91 256.26 270 top
R484  100K  [R0402]  194.46 258.17 0 top
R485  13.7K  [R0402]  198.27 257.63 180 bottom
R486  18  [R0402]  200.81 257.25 270 bottom
R487  10K  [R0402]  195.61 254.99 270 top
R488  100  [R0201]  199.64 274.7 90 top
R489  100  [R0201]  198.86 274.7 270 top
R490  49.9K  [R0402]  222.28 114.96 180 bottom
R491  49.9K  [R0402]  222.28 110.46 180 bottom
R492  0  [R0201]  222.48 131.22 180 bottom
R493  0.001  [R1206]  179.91 223.98 90 bottom
R494  0.001  [R1206]  177.62 216.81 180 bottom
R495  0  [R0402]  223.47 122.05 270 bottom
R496  0.05  [R0603]  157.56 37.62 180 bottom
R497  25.5K  [R0402]  226.95 141.78 0 bottom
R498  100  [R0201]  200.2 131.04 180 top
R499  100  [R0201]  213.28 126.97 180 top
R500  115K  [R0402]  225.7 146.99 90 bottom
R501  100  [R0201]  213.28 134.59 90 bottom
R502  100  [R0201]  215.06 134.14 90 bottom
R504  53.6K  [R0402]  110.13 268.96 270 bottom
R505  100  [R0201]  216.79 132.03 90 top
R506  0.001  [R1206]  179.37 208.43 270 bottom
R507  10K  [R0402]  200.71 192.79 180 top
R510  0  [R0201]  226.95 131.88 90 bottom
R511  0  [R0201]  226.87 136.27 270 bottom
R512  10K  [R0402]  126.31 280.09 0 top
R514  0  [R0402]  11.66 231.04 270 bottom
R515  10.2K  [R0402]  220.78 98.5 180 bottom
R516  0  [R1206]  75.01 212.73 180 top
R517  0  [R0402]  222.63 105.73 270 bottom
R518  47K  [R0402]  220.84 100.79 0 bottom
R519  10K  [R0402]  223.16 104.13 0 bottom
R520  100K  [R0402]  226.15 97.16 0 bottom
R521  49.9K  [R0402]  222.87 97.74 270 bottom
R522  10  [R0402]  215.86 94.21 180 top
R523  0.005  [R1206]  212.89 101.24 180 top
R524  0.001  [R1206]  209.11 98.95 270 top
R525  0  [R0402]  15.6 238.15 90 top
R526  0  [R0402]  24.05 273.18 90 top
R527  0  [R0402]  15.6 239.14 90 top
R528  0  [R0402]  233.55 46 0 bottom
R529  100K  [R0402]  192.56 262.23 180 top
R530  10  [R0402]  233.55 50.57 0 bottom
R531  10  [R0402]  234.19 70 0 bottom
R532  10  [R0402]  234.19 72.42 0 bottom
R533  332  [R0402]  66.9 211.53 180 bottom
R534  0  [R0402]  156.69 40.39 180 top
R535  10K  [R0402]  171.35 39.24 90 bottom
R536  40.2K  [R0402]  168.55 45.08 180 bottom
R537  10  [R0402]  167.54 36.32 180 bottom
R538  143K  [R0603]  167.82 37.97 0 top
R539  309K  [R0402]  112.4 270.64 0 bottom
R540  10  [R0402]  227.61 150.52 90 top
R541  0.1  [R0402]  231.27 180.98 0 top
R542  0  [R0402]  159.08 273 270 bottom
R543  10  [R0402]  204.24 222.43 0 top
R544  10  [R0402]  204.37 217.86 0 top
R545  10  [R0402]  204.37 213.16 0 top
R546  0  [R1206]  88.34 212.87 180 top
R547  10  [R0402]  133.91 244.83 180 top
R548  10  [R0402]  210.64 151.82 0 bottom
R549  10  [R0402]  211.18 161.87 0 bottom
R550  0  [R1206]  109.5 255.6 270 top
R551  332  [R0402]  80.24 211.68 180 bottom
R552  10  [R0402]  104.93 237.47 90 top
R553  10  [R0402]  109.25 237.57 90 top
R554  10  [R0402]  112.98 237.57 90 top
R555  10  [R0402]  204.04 111.81 90 top
R556  4.7  [R0201]  157.96 51.33 180 top
R557  4.7  [R0201]  169.75 229.03 180 bottom
R558  4.7  [R0201]  169.88 233.2 180 bottom
R559  4.7  [R0201]  169.65 221.59 180 bottom
R560  4.7  [R0201]  170.38 225.5 180 bottom
R561  0  [R0402]  142.11 103.35 180 bottom
R562  0.001  [R1206]  147.55 232.56 270 bottom
R563  4.7  [R0201]  200.04 98.11 0 top
R564  4.7  [R0201]  179.31 59.66 0 top
R565  4.7  [R0201]  196.11 85.31 0 top
R566  4.7  [R0201]  196.72 69.65 270 top
R567  4.7  [R0201]  183.03 78.78 180 top
R568  4.7  [R0201]  161.9 248.08 0 bottom
R569  4.7  [R0201]  203 157.71 0 bottom
R570  4.7  [R0201]  203.3 168.25 0 bottom
R571  4.7  [R0201]  180.81 54.85 0 top
R572  4.7  [R0201]  166.88 203.63 180 bottom
R573  4.7  [R0201]  229.67 169.21 0 top
R574  4.7  [R0201]  225.32 168.58 180 top
R575  4.7  [R0201]  166.14 215.65 180 bottom
R576  4.7  [R0201]  76.23 101.17 180 top
R577  0  [R0201]  216.38 138.51 90 bottom
R578  1  [R0201]  220.85 57.1 180 bottom
R579  10K  [R0402]  194.67 195.91 270 bottom
R581  0  [R0201]  111.33 160.45 180 bottom
R582  0  [R0402]  111.48 159.21 180 bottom
R583  0  [R0402]  111.48 158.06 180 bottom
R584  0  [R0402]  111.48 156.92 180 bottom
R585  909  [R0402]  104.01 255.04 180 top
R586  10K  [R0402]  147.93 29.59 270 top
R587  0  [R0402]  146.23 103.35 180 bottom
R588  0  [R0402]  144.22 103.35 0 bottom
R589  0  [R0402]  140.08 103.35 0 bottom
R590  10K  [R0402]  138.71 10.31 0 top
R591  0  [R0402]  69.9 87.96 270 top
R592  0  [R0402]  67.61 87.96 270 top
R593  0  [R0402]  71.3 87.96 270 top
R594  0  [R0402]  68.73 87.96 270 top
R595  10K  [R0402]  112.27 153.54 180 bottom
R596  1  [R0201]  207.01 143.05 270 bottom
R597  0  [R0201]  216.61 118.31 90 top
R598  0  [R0201]  215.42 118.31 90 top
R599  10K  [R0201]  216.61 119.99 270 top
R600  10K  [R0201]  215.44 119.99 270 top
R601  49.9K  [R0201]  221.59 126.26 0 top
R602  10K  [R0402]  207.09 114.53 0 bottom
R603  10K  [R0402]  204.06 111.81 90 bottom
R604  10K  [R0402]  208.1 113.26 180 bottom
R605  2.1K  [R0402]  206.55 115.49 0 top
R606  1  [R0201]  216.31 139.67 180 bottom
R607  1  [R0201]  235.36 131.24 90 bottom
R608  1  [R0201]  226.62 135.28 0 bottom
R609  0  [R0201]  216.89 133.78 0 bottom
R615  100K  [R0402]  100.81 238.28 90 bottom
R616  100K  [R0402]  107.67 239.19 270 bottom
R617  0  [R0402]  98.09 255.91 0 bottom
R618  0  [R0402]  110.69 238.18 90 bottom
R619  0  [R0402]  98.12 253.31 0 bottom
R620  0  [R0402]  98.15 254.51 0 bottom
R621  100K  [R0402]  111.81 239.22 270 bottom
R622  0  [R0201]  218.14 133.78 180 bottom
R623  0  [R0201]  219.51 133.78 0 bottom
R624  0  [R0201]  208.15 134.54 270 bottom
R625  0  [R0201]  208.71 134.54 270 bottom
R626  1K  [R0402]  224.54 122 90 bottom
R627  10K  [R0402]  226.87 124.71 0 top
R628  10K  [R0402]  207.77 118.59 180 bottom
R629  0  [R0402]  229.34 133.68 0 top
R630  10K  [R0402]  229.06 124.71 180 top
R631  1  [R0201]  219.48 126.14 180 top
R632  49.9K  [R0201]  222.71 126.26 0 top
R633  0  [R0402]  210.57 111.07 0 bottom
R634  0  [R0402]  204.44 114.78 180 bottom
R635  10K  [R0402]  210.77 114.53 180 bottom
R636  10K  [R0402]  200.84 115.14 90 bottom
R637  10K  [R0402]  22.76 88.6 0 top
R638  0  [R0402]  56.01 235.81 0 bottom
R639  0  [R0402]  61.47 235.64 180 bottom
R640  665  [R0402]  142.65 245.47 90 top
R641  665  [R0402]  148.56 245.87 90 top
R642  665  [R0402]  135.81 245.9 90 top
R643  0  [R0402]  224.54 224.64 0 top
R644  0  [R1206]  198.22 212.73 180 top
R645  0  [R0201]  211.33 134.65 270 bottom
R646  0  [R0201]  209.22 118.06 90 top
R647  0  [R0201]  210.03 118.08 90 top
R648  0  [R0201]  212.09 134.62 270 bottom
R649  0  [R0201]  210.74 134.62 270 bottom
R650  1K  [R0201]  212.75 118.74 180 bottom
R651  0  [R0201]  212.7 119.38 0 bottom
R652  0  [R0201]  212.65 134.59 270 bottom
R653  5.49K  [R0402]  210.57 121.44 90 top
R654  0  [R0201]  213.89 114.15 180 top
R655  0  [R0201]  206.2 134.52 270 bottom
R656  0  [R0201]  205.64 134.52 270 bottom
R657  0  [R0201]  198.42 129.92 0 bottom
R658  1  [R0201]  211.51 126.92 0 top
R659  49.9K  [R0201]  222.2 119.81 270 top
R660  49.9K  [R0201]  221.59 119.81 90 top
R661  0  [R0201]  198.35 128.42 0 bottom
R662  0  [R0201]  198.37 125.76 0 bottom
R663  0  [R0201]  198.4 126.44 0 bottom
R664  0  [R0201]  202.36 134.37 0 bottom
R665  1K  [R0201]  219.23 134.77 90 bottom
R666  1K  [R0201]  218.41 134.77 90 bottom
R667  0  [R0201]  220.8 133.78 180 bottom
R668  0  [R0201]  210.01 134.49 270 bottom
R669  0  [R0201]  209.42 134.49 270 bottom
R670  0  [R0201]  206.91 133.96 270 bottom
R671  0  [R0201]  205.49 144.81 270 bottom
R672  0  [R0201]  202.21 119.68 90 top
R673  0  [R0201]  202.82 119.74 90 top
R676  1K  [R0201]  205.49 119.84 0 bottom
R677  0  [R0201]  206.12 119.13 180 bottom
R679  5.49K  [R0402]  205.64 121.26 0 top
R680  0  [R0402]  106.15 272.97 270 bottom
R681  750  [R0201]  105.99 274.5 180 bottom
R682  0  [R0201]  207.31 141.53 0 bottom
R683  0  [R0201]  235.64 134.65 180 bottom
R684  1  [R0201]  205.82 126.95 0 top
R685  49.9K  [R0201]  222.12 116.69 270 top
R686  49.9K  [R0201]  221.51 116.69 90 top
R687  10K  [R0402]  19.02 108.64 270 top
R703  10K  [R0201]  210.01 119.76 270 top
R704  1  [R0201]  201.47 136.7 180 bottom
R705  1  [R0201]  205.77 136.68 180 bottom
R706  1  [R0201]  199.54 136.7 0 bottom
R707  1  [R0201]  203.86 136.65 0 bottom
R708  10K  [R0201]  204.04 120.42 180 bottom
R709  50  [R0402]  206.22 157.35 0 bottom
R710  50  [R0402]  207.01 166.67 0 bottom
R711  100K  [R0402]  102.64 13.21 270 bottom
R712  100K  [R0402]  101.27 13.21 270 bottom
R713  0  [R0201]  34.85 255.45 180 bottom
R714  0  [R0201]  33.73 255.45 0 bottom
R715  100  [R0402]  5.82 228.14 180 top
R716  0  [R0402]  139.62 102.9 270 bottom
R717  0  [R0402]  146.74 102.87 270 bottom
R718  0  [R0402]  142.6 102.87 270 bottom
R719  0  [R0402]  143.69 102.77 270 bottom
R720  39.2  [R0402]  27.38 195.45 180 bottom
R721  39.2  [R0402]  27.38 194.18 180 bottom
R722  100  [R0402]  25.86 194.79 270 bottom
R723  0  [R0402]  36.88 205.99 90 bottom
R724  0  [R0402]  35.71 205.99 90 bottom
R725  0  [R0402]  43.13 201.73 90 bottom
R726  0  [R0402]  41.99 201.73 90 bottom
R727  10  [R0402]  148.34 269.32 0 bottom
R728  10  [R0402]  134.92 269.7 0 bottom
R729  0.1  [R0201]  113.89 173.46 90 bottom
R730  0.1  [R0201]  126.37 168.76 90 bottom
R731  0.1  [R0201]  134.04 173.71 90 bottom
R732  0  [R0402]  27.99 204.14 90 bottom
R733  0  [R0402]  26.8 204.14 90 bottom
R734  330  [R0402]  41.07 192.68 90 top
R735  100  [R0402]  33.71 204.42 0 bottom
R736  10K  [R0402#2]  7.52 186.82 0 top
R737  10K  [R0402#2]  10.06 186.82 0 top
R738  10K  [R0402#2]  12.62 186.84 0 top
R739  10K  [R0402#2]  15.14 186.89 0 top
R740  0  [R0402]  27.2 198.93 180 bottom
R741  0  [R0402]  40.49 196.52 0 bottom
R742  0  [R0402]  40.51 197.61 0 bottom
R743  0  [R0402]  41.2 206.1 90 bottom
R744  0  [R0402]  40.08 206.1 90 bottom
R745  0  [R0402]  27.18 197.74 180 bottom
R746  0  [R0402]  156.06 256.11 180 bottom
R747  0  [R0402]  157.07 254.97 180 bottom
R748  0  [R0402]  156.06 258.39 180 bottom
R749  0  [R0402]  31.9 205.74 90 bottom
R750  0  [R0402]  30.78 205.77 90 bottom
R751  0  [R0402]  27.41 201.47 180 bottom
R752  0  [R0402]  27.38 200.18 180 bottom
R753  0  [R0402]  157.07 257.25 180 bottom
R754  0  [R0402]  156.06 260.68 180 bottom
R755  0  [R0402]  157.07 259.54 180 bottom
R756  0.001  [R1206]  132.33 229.77 270 bottom
R757  665  [R0402]  168.3 263.27 90 top
R758  0.002  [R0805]  174.04 273.41 270 top
R759  665  [R0402]  175.16 263.75 90 top
R760  0.002  [R0805]  165.38 273.38 270 top
R761  0  [R0402]  157.94 273 270 bottom
R762  665  [R0402]  161.29 264.74 270 top
R763  0  [R0402]  160.22 273 270 bottom
R764  10  [R0402]  160.5 262.71 180 top
R765  0  [R0402]  181.46 256.24 0 bottom
R766  0  [R0402]  180.44 257.38 0 bottom
R767  0  [R0402]  181.33 259.03 0 bottom
R768  0  [R0402]  180.31 260.17 0 bottom
R769  0  [R0402]  181.33 253.82 0 bottom
R770  0  [R0402]  180.31 254.97 0 bottom
R771  0  [R0402]  181.33 261.44 0 bottom
R772  0  [R0402]  180.31 262.59 0 bottom
R773  0  [R0402]  181.33 251.41 0 bottom
R774  0  [R0402]  180.31 252.55 0 bottom
R775  0  [R0402]  181.33 263.86 0 bottom
R776  0  [R0402]  180.31 265 0 bottom
R777  0.001  [R1206]  163.96 250.34 270 bottom
R778  38.3K  [R0402]  225.25 190.8 0 bottom
R779  0  [R1206]  213.16 181.18 180 top
R780  56.2  [R0402]  27.3 196.55 180 bottom
R781  56.2  [R0402]  27.38 192.94 180 bottom
R782  0  [R0402]  24.03 272.19 270 top
R783  0  [R0402]  22.78 272.19 270 top
R784  0  [R1206]  89.46 264.92 270 bottom
R786  10K  [R0201]  103.05 256.54 90 top
R787  10K  [R0201]  104.11 253.77 180 top
R788  100  [R0402]  214.2 115.16 0 top
R789  0  [R0402]  172.87 262.89 90 top
R794  100K  [R0402]  93.95 280.04 270 top
R797  48.7K  [R0402#2]  95.1 277.93 90 top
R807  76.8K  [R0402]  91.87 272.75 0 top
R808  280K  [R0402#2]  86.54 263.32 180 bottom
R809  160K  [R0402#2]  86.13 264.54 90 bottom
R810  100K  [R0402]  93.65 267.87 90 bottom
R811  0  [R0402]  94.11 269.52 0 bottom
R815  0  [R0201]  92 257.18 270 top
R816  0  [R0201]  93.27 257.43 180 top
REFCLK  142-0701-201  [CNJOHNSON142-0701-201]  51.84 217.37 180 top
REFN  142-0701-201  [CNJOHNSON142-0701-201]  62.96 277.06 0 top
REFP  142-0701-201  [CNJOHNSON142-0701-201]  78.59 277.12 0 top
RFOUT_2N  85305-0232  [CNSMASQ197H161]  144.27 217.53 270 bottom
RFOUT_2P  85305-0232  [CNSMASQ197H161]  154.08 217.53 90 bottom
S1  7914G-1-000E  [SWSMSQ197H165-2]  14.78 49.99 180 top
S2  7914G-1-000E  [SWSMSQ197H165-2]  159.51 92.23 180 top
S3  7914G-1-000E  [SWSMSQ197H165-2]  228.57 129.29 90 top
S4  1201M2S3AQE2  [SWTHRAL500W900H450]  185.83 273.02 0 top
S5  CTS206-4  [SWDIP8H335]  7.09 176.38 0 top
T1  BAL-0020SLG  [TSML500W200H110]  172.83 184.7 225 bottom
T1WA  BAL-0020SLG  [TSML500W200H110]  78.68 146.38 330 top
T1WB  BAL-0020SLG  [TSML500W200H110]  166.04 146.52 210 top
T1XA  BAL-0020SLG  [TSML500W200H110]  74.23 134.16 350 top
T1XB  BAL-0020SLG  [TSML500W200H110]  170.49 134.3 190 top
T1YA  BAL-0020SLG  [TSML500W200H110]  74.23 121.15 10 top
T1YB  BAL-0020SLG  [TSML500W200H110]  170.49 121.29 170 top
T1ZA  BAL-0020SLG  [TSML500W200H110]  78.68 108.92 30 top
T1ZB  BAL-0020SLG  [TSML500W200H110]  166.04 109.06 150 top
T2  BAL-0020SLG  [TSML500W200H110]  71.97 184.72 315 bottom
T3  BAL-0020SLG  [TSML500W200H110]  122.71 187.4 270 bottom
T4  TCM2-43X+  [TSML150W160H160]  43.74 218.59 270 top
TP1  TESTPAD  [TPSMC30]  64.19 228.32 0 top
TP2  TESTPAD  [TPSMC30]  147.65 282.88 0 top
TP3  TESTPAD  [TPSMC30]  134.82 282.75 0 top
TP4  TESTPAD  [TPSMC30]  210.44 178.36 180 top
TP5  TESTPAD  [TPSMC30]  212.93 178.49 180 top
TP6  TESTPAD  [TPSMC30]  217.5 178.38 180 top
TP7  TESTPAD  [TPSMC30]  215.67 178.46 180 top
TP8  TESTPAD  [TPSMC30]  185.57 230.07 0 top
TP9  TESTPAD  [TPSMC30]  178.89 219.05 0 top
TP10  TESTPAD  [TPSMC30]  179.81 213.44 0 top
TP11  TESTPAD  [TPSMC30]  206.15 222.43 0 top
TP12  TESTPAD  [TPSMC30]  206.27 213.16 90 top
TP13  TESTPAD  [TPSMC30]  206.27 217.86 0 top
TP15  TESTPAD  [TPSMC30]  134.67 246.35 180 top
TP16  TESTPAD  [TPSMC30]  132.08 244.86 90 top
TP17  TESTPAD  [TPSMC30]  210.77 159.31 0 top
TP18  TESTPAD  [TPSMC30]  214.03 94.23 270 top
TP19  TESTPAD  [TPSMC30]  217.22 82.37 270 top
TP20  TESTPAD  [TPSMC30]  218.74 76.87 0 top
TP21  TESTPAD  [TPSMC30]  165.23 36.7 180 top
TP22  TESTPAD  [TPSMC30]  226.19 151.74 180 top
TP23  TESTPAD  [TPSMC30]  209.4 149.02 0 top
TP24  TESTPAD  [TPSMC30]  213.03 151.21 0 top
TP25  TESTPAD  [TPSMC30]  213.11 161.85 0 top
TP26  TESTPAD  [TPSMC30]  67.44 208.69 0 top
TP27  TESTPAD  [TPSMC30]  116.61 262.23 0 top
TP28  TESTPAD  [TPSMC30]  101.12 246.46 180 top
TP29  TESTPAD  [TPSMC30]  80.7 208.79 0 top
TP30  TESTPAD  [TPSMC30]  105.16 239.5 90 top
TP31  TESTPAD  [TPSMC30]  109.25 239.48 90 top
TP32  TESTPAD  [TPSMC30]  112.98 239.48 180 top
TP33  TESTPAD  [TPSMC30]  204.04 113.46 180 top
TP34  TESTPAD  [TPSMC30]  101.02 244.81 0 top
TP35  TESTPAD  [TPSMC30]  117.55 250.57 0 top
TP36  TESTPAD  [TPSMC30]  159.44 264.29 180 top
TP37  TESTPAD  [TPSMC30]  158.67 262.74 90 top
TP39  TESTPAD  [TPSMC30]  176.83 264.29 0 top
TP40  TESTPAD  [TPSMC30]  30.35 108.94 0 top
TP41  TESTPAD  [TPSMC30]  31.55 107.29 0 top
TP42  TESTPAD  [TPSMC40]  39.8 188.6 90 bottom
TP43  TESTPAD  [TPSMC40]  24.71 188.49 90 bottom
TP44  TESTPAD  [TPSMC40]  45.59 192.76 90 bottom
TP45  TESTPAD  [TPSMC40]  45.62 194.77 90 bottom
TP46  TESTPAD  [TPSMC40]  43.92 195.99 90 bottom
TP47  TESTPAD  [TPSMC40]  43.89 197.87 90 bottom
TP48  TESTPAD  [TPSMC40]  41.61 208.13 180 bottom
TP49  TESTPAD  [TPSMC40]  39.42 208.1 180 bottom
TP50  TESTPAD  [TPSMC40]  37.13 208.18 90 bottom
TP51  TESTPAD  [TPSMC40]  35.23 208.2 90 bottom
TP52  TESTPAD  [TPSMC40]  43.74 203.76 180 bottom
TP53  TESTPAD  [TPSMC40]  41.73 203.78 180 bottom
TP54  TESTPAD  [TPSMC40]  28.42 206.15 0 bottom
TP55  TESTPAD  [TPSMC40]  26.49 206.15 0 bottom
TP56  TESTPAD  [TPSMC40]  32.28 207.87 180 bottom
TP57  TESTPAD  [TPSMC40]  30.28 207.85 180 bottom
TP58  TESTPAD  [TPSMC30]  32.64 108.66 0 top
TP59  TESTPAD  [TPSMC30]  23.65 107.92 0 top
TP60  TESTPAD  [TPSMC40]  25.27 199.24 90 bottom
TP61  TESTPAD  [TPSMC40]  25.25 197.33 90 bottom
TP62  TESTPAD  [TPSMC40]  23.22 201.88 90 bottom
TP63  TESTPAD  [TPSMC40]  23.22 199.92 90 bottom
TP64  TESTPAD  [TPSMC30]  33.6 110.06 0 top
TP65  TESTPAD  [TPSMC30]  150.06 247.98 0 top
TP78  TESTPAD  [TPSMC40]  84.86 282.52 0 top
U1  LTM4702EY#PBF  [BGA49H211]  225.03 101.22 270 top
U1A  AD9088_8T8R_SE_B0  [BGA899]  122.3 125.73 180 top
U1B  HMC7044LP10BE  [QFN68_10X10_PAD6_3X6_3]  16.61 224.09 90 bottom
U2  LTC6955IUKG#PBF  [QFN52_8X7_PAD6_45X5_41]  56.18 229.84 180 bottom
U3  ADP124ACPZ-1.8  [QFN8_2X2_PAD1_6X1]  152.93 39.7 90 bottom
U4  LT3045EDD#PBF  [DFN10_3X3_PAD2_38X1_64]  81.74 214.93 180 bottom
U5  LTM4702EY#PBF  [BGA49H211]  132.03 273.61 0 top
U6  LTM8074EY#PBF  [BGA25_4X4]  226.95 144.22 180 top
U7  LTM4709HY  [BGA98_12X6]  141.78 247.12 0 bottom
U8  LTM4709HY  [BGA98_12X6]  190.27 217.86 270 bottom
U9  LT3094EDD#PBF  [DFN12_3X3_PAD2_38X1_65]  207.21 152.1 270 bottom
U10  LT3094EDD#PBF  [DFN12_3X3_PAD2_38X1_65]  208 162.1 270 bottom
U11  LTC2980IY-24#PBF  [BGA210_16_9X8_1]  209.85 126.95 180 bottom
U12  ADG772BCPZ  [QFN10_1_6X1_3]  98.51 6.86 0 top
U13  ADG772BCPZ  [QFN10_1_6X1_3]  132.51 6.64 270 top
U14  ADG772BCPZ  [QFN10_1_6X1_3]  91.19 6.97 90 top
U15  ADG772BCPZ  [QFN10_1_6X1_3]  105.88 6.86 180 top
U16  ADG772BCPZ  [QFN10_1_6X1_3]  116.73 6.96 0 top
U17  ADG772BCPZ  [QFN10_1_6X1_3]  127.74 6.67 270 top
U18  ADG772BCPZ  [QFN10_1_6X1_3]  110.43 6.88 0 top
U19  ADG772BCPZ  [QFN10_1_6X1_3]  123.42 6.27 0 top
U20  M24C02-FDW6TP  [TSSOP8]  101.32 12.78 270 top
U21  USBULC6-2M6  [UQFN6_1_45X1]  7.92 59.18 270 top
U22  CP2105-F01-GM  [QFN24_4X4_PAD2_7X2_7]  12.29 59.13 270 top
U23  FXLA104UM12X  [MLP12_1_8X1_8]  66.63 45.89 180 top
U24  FXLA104UM12X  [MLP12_1_8X1_8]  66.63 41.66 180 top
U25  FXLA104UM12X  [MLP12_1_8X1_8]  48.92 83.76 180 top
U26  FXLA104UM12X  [MLP12_1_8X1_8]  48.93 79.53 180 top
U27  FXLA104UM12X  [MLP12_1_8X1_8]  82.13 66.16 90 top
U28  FXLA104UM12X  [MLP12_1_8X1_8]  77.91 66.16 90 top
U29  FXLA104UM12X  [MLP12_1_8X1_8]  67.38 66.19 90 top
U30  ADF4382  [LGA48_7X7_PAD2_375X2_375]  123.95 156.21 270 bottom
U31  LTM4702EY#PBF  [BGA49H211]  144.86 273.61 0 top
U32  LTM8051EY#PBF  [BGA91_11_25X6_25]  221.54 187.25 180 top
U33  LTM4681IY#PBF  [BGA330_22X15H337]  220.34 59.72 90 top
U34  LTM4709HY  [BGA98_12X6]  108.23 247.27 0 bottom
U35  MC74LCX16244DTG  [TSSOP48]  15.32 78.18 270 top
U36  LTM4702EY#PBF  [BGA49H211]  109.63 273.23 0 top
U37  LT6658AHDE-1.2#TRPBF  [DFN16_4X3_PAD3_3X1_7]  197.54 194.08 270 bottom
U38  LT3045EDD#PBF  [DFN10_3X3_PAD2_38X1_64]  68.4 214.76 180 bottom
U39  LTC4210-2IS6#TRMPBF  [TSOT23_6]  199.81 261.67 180 bottom
U40  LTM8074EY#PBF  [BGA25_4X4]  167.41 41.02 180 bottom
U41  FXLA104UM12X  [MLP12_1_8X1_8]  69.27 84.02 90 top
U42  FXLA104UM12X  [MLP12_1_8X1_8]  63.15 66.19 90 top
U43  FXLA104UM12X  [MLP12_1_8X1_8]  82.06 83.23 90 top
U44  FXLA104UM12X  [MLP12_1_8X1_8]  77.83 83.23 90 top
U45  FXLA104UM12X  [MLP12_1_8X1_8]  36.39 100.76 90 top
U46  FXLA104UM12X  [MLP12_1_8X1_8]  32.16 100.76 90 top
U47  FXLA104UM12X  [MLP12_1_8X1_8]  21.58 100.84 90 top
U48  FXLA104UM12X  [MLP12_1_8X1_8]  17.35 100.83 90 top
U49  125 MHZ  [YSML560W360H210_6P]  81.76 233.32 180 bottom
U50  SN74LVC1GU04DCKT  [SC70-5]  38.4 193.8 270 top
U51  ADF4030  [LGA48_7X7_PAD2_375X2_375]  33.76 199.29 90 bottom
U52  LTM4709HY  [BGA98_12X6]  168.38 265 0 bottom
U53  ADP7112ACBZ-5.0-R7  [WLCSP6_B]  230.3 196.82 0 top
U54  ADP124ACPZ-1.8  [QFN8_2X2_PAD1_6X1]  155.7 47.24 90 bottom
U72  LTM8053EY#PBF  [BGA48H139]  90.63 275.97 180 bottom
U73  ADP7159ACPZ-04-R7  [DFN10_3X3_PAD2_38X1_64]  87.76 259.54 180 bottom
U74  ADP7112ACBZ-1.8-R7  [WLCSP6_B]  91.19 258.44 0 bottom
UNK1P8V  WHT  [CNKEY5001TP]  62.05 82.75 0 top
UNK3P3V  WHT  [CNKEY5001TP]  26.97 75.34 0 top
UNK12P0V  WHT  [CNKEY5001TP]  205.03 282.7 180 top
UNK80A_V0  TESTPAD  [TPSMC30]  212.7 114.15 0 top
UNK80B_V4  TESTPAD  [TPSMC30]  202.23 134.9 0 top
Y1  125MEGHZ  [LCC4H210]  28.37 238.17 90 bottom
Y3  125MEGHZ  [LCC4H210]  81.76 233.32 180 bottom

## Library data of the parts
A1 A2 = ADLT1990_10: Tolerance: N/A; User Part Number: UPN; alternate symbols: (MSOP8); part number: ADLT1990_10_SM-LT1990IMS8-10#PBF,E059816,MSOP8; tolerance: N/A
A3 = ADLT1990: User Part Number: UPN; Tolerance: N/A; alternate symbols: (SO8NB-5); part number: ADLT1990_SM-LT1990HS8#PBF,E040655,SO8NB-5; tolerance: N/A
A4 = ADLT1990: Tolerance: N/A; User Part Number: UPN; alternate symbols: (SO8NB-5); part number: ADLT1990_SM-LT1990HS8#PBF,E040655,SO8NB-5; tolerance: N/A
ADC_A0-ADC_A3 ADC_B0-ADC_B3 DACA0-DACA3 DACB0-DACB3 = CN1P_1GND: User Part Number: UPN; Tolerance: N/A; alternate symbols: (CNAMPHENOLSF1521-60070-XS_RF2); part number: CN1P_1GND_SM-SF1521-60070-1S,E035995,CNAMPHENOLSF1521-60070-XS; tolerance: N/A
BUFDIS PWRDBG = CN2P: Tolerance: N/A; User Part Number: UPN; alternate symbols: (CNSAMTECTMM-102-01-G-S-SM); part number: CN2P_SM-TMM-102-01-G-S-SM,E011177,CNSAMTECTMM-102-01-G-S-SM; tolerance: N/A
C1-C3 C3WA C3WB C3XA C3XB C3YA C3YB C3ZA C3ZB C4 C4WA C4WB C4XA C4XB C4YA C4YB C4ZA C4ZB C5 C5WA C5WB C5XA C5XB C5YA C5YB C5ZA C5ZB C6 C6WA C6WB C6XA C6XB C6YA C6YB C6ZA C6ZB C7 C7WA C7WB C7XA C7XB C7YA C7YB C7ZA C7ZB C8-C78 C80-C90 C92-C97 C105 C113 C120 C145-C149 C151 C152 C154-C156 C168 C172-C174 C176 C204 C206 C208-C221 C223 C226-C234 C237 C257 C258 C261 C265 C269 C316 C317 C323-C325 C328-C335 C337 C338 C340 C343 C345 C348 C350-C355 C358 C360 C363 C365 C368-C371 C373-C375 C378-C382 C384-C391 C393-C398 C401-C406 C408 C409 C411-C416 C418-C425 C428 C430-C434 C438 C440-C445 C447 C448 C450-C454 C456-C471 C474-C481 C485 C490-C497 C502 C508-C511 C522 C523 C538-C544 C547-C552 C554-C571 C618-C620 C623-C628 C630-C638 C665 C668 C671 C678 C683 C691-C703 C706 C709-C720 C722 C723 C748 C749 C765 C766 = CAP: Tolerance: 10; User Part Number: UPN; alternate symbols: (C0201L); part number: CAP_SM-0.1UF,16V,10,E041991,C0201; tolerance: 10
C1WA C1WB C1XA C1XB C1YA C1YB C1ZA C1ZB C2WA C2WB C2XA C2XB C2YA C2YB C2ZA C2ZB C132 C143 C150 C166 C167 C169 C171 C175 C235 C245 C247 C248 C429 C435 C648 C649 = CAP: User Part Number: UPN; Tolerance: 10; alternate symbols: (C0603); part number: CAP_SM-1UF,25V,10,E033832,C0603; tolerance: 10
C79 C91 C250 C251 C254 C256 C260 C266-C268 C270-C278 C326 C327 C526 C527 C530 C662 C674 C677 C679-C682 C684-C690 C721 = CAP: User Part Number: UPN; Tolerance: 10; alternate symbols: (C0201L); part number: CAP_SM-0.1UF,16V,10,E041991,C0201; tolerance: 10
C98 C99 C101 C102 C107 C110 C134 C195 C574 C575 C864 = CAP: User Part Number: UPN; Tolerance: 20; alternate symbols: (C0402); part number: CAP_SM-4.7UF,6.3V,20,E014207,C0402; tolerance: 20
C100 C103 C129 C163 C222 C225 C280 C282 C284 C286 C287 C289 C292 C295 C297 C299 C301 C303 C305 C307 C309 C320-C322 C606 C707 C708 C753 C763 C764 = CAP: User Part Number: UPN; Tolerance: 10; alternate symbols: (C0402); part number: CAP_SM-1UF,10V,10,E028140,C0402; tolerance: 10
C104 = CAP: User Part Number: UPN; Tolerance: 5; alternate symbols: (C0402); part number: CAP_SM-100PF,50V,5,E022402,C0402; tolerance: 5
C106 C315 = CAP: Tolerance: 20; User Part Number: UPN; alternate symbols: (C0201L); part number: CAP_SM-1UF,10V,20,E022044,C0201; tolerance: 20
C108 C111 C112 C114-C119 C122 C123 C125 C130 C131 C201 C310-C314 = CAP: User Part Number: UPN; Tolerance: 10; alternate symbols: (C0402L); part number: CAP_SM-1UF,10V,10,E028140,C0402; tolerance: 10
C109 C253 = CAP: alternate symbols: (C0402L); part number: CAP_SM-1UF,10V,10,E028140,C0402; tolerance: 10
